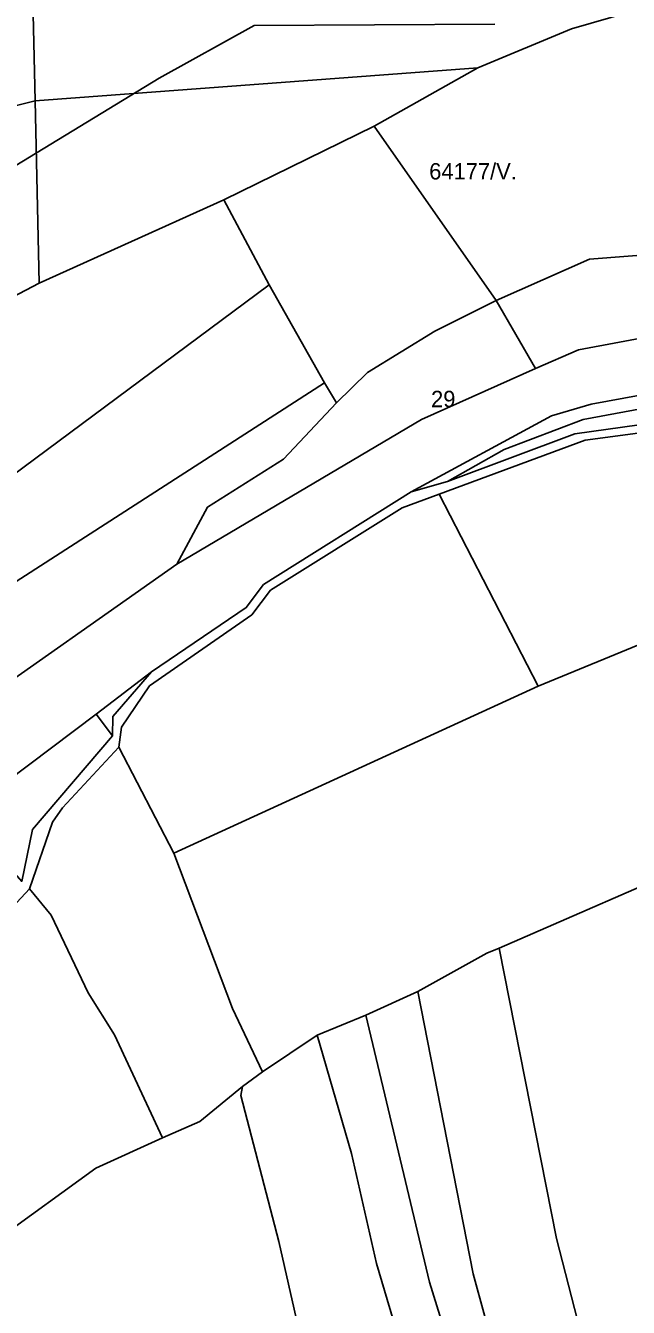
# Model space of a CAD drawing. Extents: x -521261 to -517465, y -1182764 to -1179456.
# Drawn here: x -519947.3 to -519763.3, y -1181487.6 to -1181096.5 of the extents above; entities that cross this region are included whole.
import ezdxf

# ---------------------------------------------------------------- set-up
doc = ezdxf.new("R2010")
doc.units = 0
for name, color, linetype in [('95560013', 7, 'Continuous'), ('95610013', 7, 'Continuous'), ('95620013', 7, 'Continuous'), ('95630013', 7, 'Continuous'), ('95640013', 7, 'Continuous'), ('95660013', 7, 'Continuous')]:
    doc.layers.add(name, color=color, linetype=linetype)

msp = doc.modelspace()

# ---------------------------------------------------------------- linework, layer by layer
at = {"layer": '95560013'}
for points in [[(-519776.47, -1181223), (-519744.35, -1181218.67), (-519720.31, -1181269.1), (-519790.84, -1181298.01), (-519821.08, -1181239.47)], [(-519832.32, -1181243.68), (-519821.08, -1181239.47), (-519790.84, -1181298.01), (-519902.04, -1181348.97), (-519918.79, -1181316.7), (-519918, -1181310.57), (-519909.44, -1181297.97), (-519878.23, -1181276.31), (-519872.54, -1181268.79)], [(-519790.84, -1181298.01), (-519720.31, -1181269.1), (-519695.05, -1181335.72), (-519728.59, -1181345.45), (-519738.77, -1181350.12), (-519802.77, -1181378.03), (-519806.49, -1181379.47), (-519827.57, -1181391.18), (-519843.39, -1181398.48), (-519858.26, -1181404.56), (-519875.01, -1181415.68), (-519884.18, -1181396.37), (-519902.04, -1181348.97)], [(-519936.01, -1181335.15), (-519918.79, -1181316.7), (-519902.04, -1181348.97), (-519884.18, -1181396.37), (-519875.01, -1181415.68), (-519881.06, -1181420.17), (-519894.06, -1181430.89), (-519905.49, -1181435.85), (-519920.19, -1181404.39), (-519928.16, -1181391.65), (-519939.45, -1181367.89), (-519946.1, -1181359.91), (-519939.03, -1181339.56)], [(-519802.77, -1181378.03), (-519738.77, -1181350.12), (-519717.09, -1181452.91), (-519704.33, -1181495.42), (-519696.97, -1181527.88), (-519734.21, -1181538), (-519747.84, -1181543.58), (-519759.56, -1181546.55), (-519769.64, -1181520.91), (-519777.88, -1181495.02), (-519785.24, -1181466.55)], [(-519951.3, -1181365.5), (-519946.1, -1181359.91), (-519939.45, -1181367.89), (-519928.16, -1181391.65), (-519920.19, -1181404.39), (-519905.49, -1181435.85), (-519925.87, -1181445.17), (-519955.99, -1181466.92), (-519963.8, -1181454), (-519965.32, -1181445.39), (-519965.55, -1181438.1), (-519964.94, -1181434.67), (-519961.63, -1181415.2), (-519961.5, -1181387.25), (-519958.05, -1181376.65)], [(-519806.49, -1181379.47), (-519802.77, -1181378.03), (-519785.24, -1181466.55), (-519777.88, -1181495.02), (-519769.64, -1181520.91), (-519759.56, -1181546.55), (-519780.96, -1181551.7), (-519792.84, -1181528.25), (-519803.56, -1181503.4), (-519810.65, -1181477.32), (-519827.57, -1181391.18)], [(-519843.39, -1181398.48), (-519827.57, -1181391.18), (-519810.65, -1181477.32), (-519803.56, -1181503.4), (-519792.84, -1181528.25), (-519780.96, -1181551.7), (-519799.35, -1181551.07), (-519806.94, -1181535.03), (-519823.96, -1181479.91)], [(-519858.26, -1181404.56), (-519843.39, -1181398.48), (-519823.96, -1181479.91), (-519806.94, -1181535.03), (-519799.35, -1181551.07), (-519820.94, -1181549.11), (-519832.54, -1181499.93), (-519840.21, -1181474.26), (-519847.83, -1181440.64)], [(-519858.26, -1181404.56), (-519847.83, -1181440.64), (-519840.21, -1181474.26), (-519832.54, -1181499.93), (-519820.94, -1181549.11), (-519819.03, -1181562.34), (-519836.49, -1181569.45), (-519846.63, -1181568), (-519850.41, -1181556.71), (-519852.44, -1181544.73), (-519869.95, -1181467.47), (-519881.55, -1181422.98), (-519881.06, -1181420.17), (-519875.01, -1181415.68)], [(-519881.06, -1181420.17), (-519881.55, -1181422.98), (-519869.95, -1181467.47), (-519852.44, -1181544.73), (-519850.41, -1181556.71), (-519864.72, -1181556.65), (-519890.05, -1181563.82), (-519912.71, -1181573.25), (-519943.88, -1181587.97), (-519966.4, -1181460.95), (-519963.8, -1181454), (-519955.99, -1181466.92), (-519925.87, -1181445.17), (-519905.49, -1181435.85), (-519894.06, -1181430.89)]]:
    msp.add_lwpolyline(points, close=True, dxfattribs=at)
at = {"layer": '95610013'}
for points in [[(-519739.3, -1181085.44), (-519712.94, -1181129.93), (-519700.84, -1181149.53), (-519735.12, -1181160.39), (-519742.39, -1181165.26), (-519775.16, -1181167.72), (-519803.6, -1181180.37), (-519840.89, -1181127.16), (-519809.28, -1181109.36), (-519780.6, -1181097.51)], [(-519944.34, -1181119.43), (-519809.28, -1181109.36), (-519840.89, -1181127.16), (-519886.73, -1181149.7), (-519943.14, -1181175.07)], [(-519944.34, -1181119.43), (-519943.14, -1181175.07), (-519987.58, -1181198.4), (-520040.59, -1181233.21), (-520006.04, -1181178.85), (-519990.56, -1181155.71), (-519981.67, -1181128.85)], [(-519840.89, -1181127.16), (-519803.6, -1181180.37), (-519822.38, -1181189.69), (-519842.97, -1181202.29), (-519852.38, -1181211.59), (-519856.08, -1181205.45), (-519872.92, -1181175.6), (-519886.73, -1181149.7)], [(-519856.08, -1181205.45), (-519852.38, -1181211.59), (-519868.58, -1181228.75), (-519891.75, -1181243.42), (-519901.14, -1181260.79), (-519966.9, -1181306.97), (-519979.58, -1181315.88), (-519991.48, -1181329.17), (-520027.93, -1181375.27), (-520038.45, -1181365.21), (-520015.84, -1181335.46), (-519995.54, -1181305.59), (-519971.69, -1181279.96)]]:
    msp.add_lwpolyline(points, close=True, dxfattribs=at)
at = {"layer": '95620013'}
for points in [[(-519886.73, -1181149.7), (-519872.92, -1181175.6), (-519990.97, -1181263.2), (-519998.85, -1181259.72), (-519994.9, -1181247.54), (-519974.28, -1181217.29), (-519987.58, -1181198.4), (-519943.14, -1181175.07)], [(-519872.92, -1181175.6), (-519856.08, -1181205.45), (-519971.69, -1181279.96), (-519990.97, -1181263.2)]]:
    msp.add_lwpolyline(points, close=True, dxfattribs=at)
at = {"layer": '95630013'}
msp.add_lwpolyline([(-519949.41, -1181080.84), (-519945.25, -1181079.6), (-519944.34, -1181119.43), (-519981.67, -1181128.85), (-519974.19, -1181113.01), (-519957.49, -1181098.06), (-519951.75, -1181081.08)], close=True, dxfattribs=at)
at = {"layer": '95640013'}
for points in [[(-519727.01, -1181007.89), (-519721.82, -1181010.41), (-519720.05, -1181017.36), (-519694.53, -1181072.36), (-519739.3, -1181085.44), (-519780.6, -1181097.51), (-519809.28, -1181109.36), (-519944.34, -1181119.43), (-519945.25, -1181079.6), (-519930.37, -1181075.45), (-519894.68, -1181059.82), (-519846.27, -1181042.69), (-519787.58, -1181026.69)], [(-519700.84, -1181149.53), (-519692.32, -1181164.66), (-519734.37, -1181182.89), (-519751.87, -1181190.47), (-519778.56, -1181195.39), (-519791.66, -1181201.16), (-519803.6, -1181180.37), (-519775.16, -1181167.72), (-519742.39, -1181165.26), (-519735.12, -1181160.39)], [(-519655.55, -1181156.71), (-519654.28, -1181159.23), (-519653.86, -1181160.48), (-519668.56, -1181167.09), (-519673.02, -1181170.06), (-519680.21, -1181177.92), (-519702.97, -1181185.1), (-519708.94, -1181187.08), (-519723.4, -1181194.69), (-519749.06, -1181211.51), (-519777.07, -1181216.66), (-519801.23, -1181225.82), (-519818.52, -1181235.6), (-519829.59, -1181238.74), (-519786.76, -1181215.56), (-519774.62, -1181212.01), (-519750.87, -1181207.64), (-519728.68, -1181193.73), (-519707.46, -1181181.92), (-519683.85, -1181172.43), (-519670.38, -1181163.67)], [(-519803.6, -1181180.37), (-519791.66, -1181201.16), (-519826.46, -1181216.65), (-519901.14, -1181260.79), (-519891.75, -1181243.42), (-519868.58, -1181228.75), (-519852.38, -1181211.59), (-519842.97, -1181202.29), (-519822.38, -1181189.69)], [(-519751.87, -1181190.47), (-519734.37, -1181182.89), (-519728.68, -1181193.73), (-519750.87, -1181207.64), (-519774.62, -1181212.01), (-519786.76, -1181215.56), (-519829.59, -1181238.74), (-519874.64, -1181267.05), (-519879.94, -1181274.06), (-519908.9, -1181293.64), (-519925.73, -1181306.64), (-519953.04, -1181327.12), (-519966.9, -1181306.97), (-519901.14, -1181260.79), (-519826.46, -1181216.65), (-519791.66, -1181201.16), (-519778.56, -1181195.39)], [(-519745.48, -1181216.27), (-519779.59, -1181221.04), (-519818.52, -1181235.6), (-519801.23, -1181225.82), (-519777.07, -1181216.66), (-519749.06, -1181211.51)], [(-519925.73, -1181306.64), (-519908.9, -1181293.64), (-519920.61, -1181307.26), (-519920.76, -1181313.19)], [(-519920.76, -1181313.19), (-519945.15, -1181341.8), (-519948.46, -1181357.6), (-519965.99, -1181337.63), (-519953.04, -1181327.12), (-519925.73, -1181306.64)]]:
    msp.add_lwpolyline(points, close=True, dxfattribs=at)
for points in [[(-519744.35, -1181218.67), (-519776.47, -1181223), (-519821.08, -1181239.47), (-519832.32, -1181243.68), (-519872.54, -1181268.79), (-519878.23, -1181276.31), (-519909.44, -1181297.97), (-519918, -1181310.57), (-519918.79, -1181316.7), (-519936.01, -1181335.15), (-519939.03, -1181339.56), (-519946.1, -1181359.91), (-519951.3, -1181365.5)], [(-519948.46, -1181357.6), (-519945.15, -1181341.8), (-519920.76, -1181313.19), (-519920.61, -1181307.26), (-519908.9, -1181293.64), (-519879.94, -1181274.06), (-519874.64, -1181267.05), (-519829.59, -1181238.74), (-519818.52, -1181235.6), (-519779.59, -1181221.04), (-519745.48, -1181216.27)]]:
    msp.add_lwpolyline(points, dxfattribs=at)
at = {"layer": '95660013'}
for points in [[(-519804, -1181096), (-519877.5, -1181096.5), (-519906.5, -1181112.5), (-519955, -1181142), (-519991.5, -1181172), (-520000, -1181174.62), (-520004.04, -1181175.86), (-519990.56, -1181155.71), (-519981.67, -1181128.85), (-520009.75, -1181138.53), (-520013.54, -1181182.09), (-520025.14, -1181191.93), (-520050.1, -1181223.4), (-520070.9, -1181238.45), (-520069.69, -1181252.35), (-520087.51, -1181273.69), (-520099.76, -1181280.17), (-520100.07, -1181292.11), (-520124.95, -1181307.73), (-520148.41, -1181325.86), (-520173, -1181306.5), (-520211, -1181261), (-520246, -1181224)], [(-519955, -1181142), (-519906.5, -1181112.5), (-519877.5, -1181096.5), (-519804, -1181096)], [(-519987.58, -1181198.4), (-519943.14, -1181175.07), (-519886.73, -1181149.7), (-519872.92, -1181175.6), (-519856.08, -1181205.45), (-519971.69, -1181279.96)], [(-519971.69, -1181279.96), (-519856.08, -1181205.45), (-519872.92, -1181175.6), (-519886.73, -1181149.7), (-519943.14, -1181175.07), (-519987.58, -1181198.4)], [(-519966.9, -1181306.97), (-519901.14, -1181260.79), (-519891.75, -1181243.42), (-519868.58, -1181228.75), (-519852.38, -1181211.59), (-519842.97, -1181202.29), (-519822.38, -1181189.69), (-519803.6, -1181180.37), (-519775.16, -1181167.72), (-519742.39, -1181165.26)], [(-519742.39, -1181165.26), (-519775.16, -1181167.72), (-519803.6, -1181180.37), (-519822.38, -1181189.69), (-519842.97, -1181202.29), (-519852.38, -1181211.59), (-519868.58, -1181228.75), (-519891.75, -1181243.42), (-519901.14, -1181260.79), (-519966.9, -1181306.97)], [(-519750.87, -1181207.64), (-519774.62, -1181212.01), (-519786.76, -1181215.56), (-519829.59, -1181238.74), (-519874.64, -1181267.05), (-519879.94, -1181274.06), (-519908.9, -1181293.64), (-519925.73, -1181306.64), (-519920.76, -1181313.19), (-519945.15, -1181341.8), (-519948.46, -1181357.6)], [(-519948.46, -1181357.6), (-519945.15, -1181341.8), (-519920.76, -1181313.19), (-519925.73, -1181306.64), (-519908.9, -1181293.64), (-519879.94, -1181274.06), (-519874.64, -1181267.05), (-519829.59, -1181238.74), (-519786.76, -1181215.56), (-519774.62, -1181212.01), (-519750.87, -1181207.64)]]:
    msp.add_lwpolyline(points, dxfattribs=at)

# ---------------------------------------------------------------- texts
for s, p in [('64177/V.', (-519824.09, -1181143.44)), ('29', (-519823.52, -1181212.92))]:
    msp.add_text(s, height=5, rotation=0, dxfattribs=at).set_placement(p)

doc.saveas('drawing.dxf')
